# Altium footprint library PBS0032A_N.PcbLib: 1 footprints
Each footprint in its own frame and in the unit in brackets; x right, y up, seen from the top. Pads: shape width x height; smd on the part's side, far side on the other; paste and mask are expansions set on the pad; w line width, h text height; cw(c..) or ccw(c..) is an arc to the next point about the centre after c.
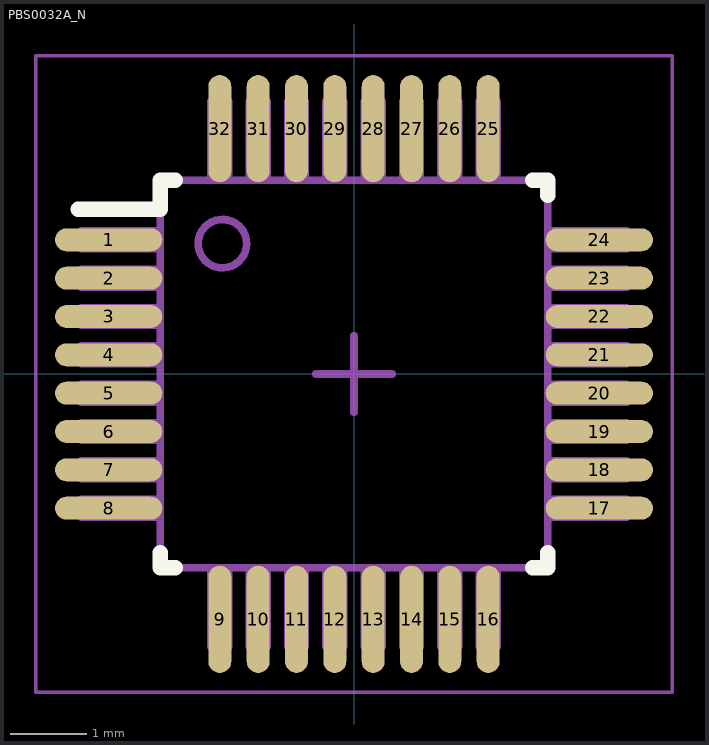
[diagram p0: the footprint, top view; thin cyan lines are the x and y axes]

## PBS0032A_N [mm]
height 1.2
pads (32):
  oval 1.4x0.3 smd: 1(-3.2,1.75) 2(-3.2,1.25) 3(-3.2,0.75) 4(-3.2,0.25) 5(-3.2,-0.25) 6(-3.2,-0.75) 7(-3.2,-1.25) 8(-3.2,-1.75) 17(3.2,-1.75) 18(3.2,-1.25) 19(3.2,-0.75) 20(3.2,-0.25) 21(3.2,0.25) 22(3.2,0.75) 23(3.2,1.25) 24(3.2,1.75)
  oval 0.3x1.4 smd: 9(-1.75,-3.2) 10(-1.25,-3.2) 11(-0.75,-3.2) 12(-0.25,-3.2) 13(0.25,-3.2) 14(0.75,-3.2) 15(1.25,-3.2) 16(1.75,-3.2) 25(1.75,3.2) 26(1.25,3.2) 27(0.75,3.2) 28(0.25,3.2) 29(-0.25,3.2) 30(-0.75,3.2) 31(-1.25,3.2) 32(-1.75,3.2)
Top Overlay:
  lines w0.2: -3.6,2.15 -2.527,2.15 -2.527,2.527 -2.327,2.527 ; -2.527,-2.327 -2.527,-2.527 -2.327,-2.527 ; 2.327,-2.527 2.527,-2.527 2.527,-2.327 ; 2.327,2.527 2.527,2.527 2.527,2.327
Mechanical 5:
  circle w0.1: c-1.716,1.7 r0.316
  lines w0.1: -3.556,-1.864 -3.556,-1.636 -2.527,-1.636 -2.527,-1.864 -3.556,-1.864 ; -3.556,-1.364 -3.556,-1.136 -2.527,-1.136 -2.527,-1.364 -3.556,-1.364 ; -3.556,-0.864 -3.556,-0.636 -2.527,-0.636 -2.527,-0.864 -3.556,-0.864 ; -3.556,-0.364 -3.556,-0.136 -2.527,-0.136 -2.527,-0.364 -3.556,-0.364 ; -3.556,0.136 -3.556,0.364 -2.527,0.364 -2.527,0.136 -3.556,0.136 ; -3.556,0.636 -3.556,0.864 -2.527,0.864 -2.527,0.636 -3.556,0.636 ; -3.556,1.136 -3.556,1.364 -2.527,1.364 -2.527,1.136 -3.556,1.136 ; -3.556,1.636 -3.556,1.864 -2.527,1.864 -2.527,1.636 -3.556,1.636 ; -2.527,-2.527 2.527,-2.527 2.527,2.527 -2.527,2.527 -2.527,-2.527 ; -1.864,-3.556 -1.864,-2.527 -1.636,-2.527 -1.636,-3.556 -1.864,-3.556 ; -1.864,2.527 -1.636,2.527 -1.636,3.556 -1.864,3.556 -1.864,2.527 ; -1.364,-3.556 -1.364,-2.527 -1.136,-2.527 -1.136,-3.556 -1.364,-3.556 ; -1.364,2.527 -1.136,2.527 -1.136,3.556 -1.364,3.556 -1.364,2.527 ; -0.864,-3.556 -0.864,-2.527 -0.636,-2.527 -0.636,-3.556 -0.864,-3.556 ; -0.864,2.527 -0.636,2.527 -0.636,3.556 -0.864,3.556 -0.864,2.527 ; -0.364,-3.556 -0.364,-2.527 -0.136,-2.527 -0.136,-3.556 -0.364,-3.556 ; -0.364,2.527 -0.136,2.527 -0.136,3.556 -0.364,3.556 -0.364,2.527 ; 0.136,-3.556 0.136,-2.527 0.364,-2.527 0.364,-3.556 0.136,-3.556 ; 0.136,2.527 0.364,2.527 0.364,3.556 0.136,3.556 0.136,2.527 ; 0.636,-3.556 0.636,-2.527 0.864,-2.527 0.864,-3.556 0.636,-3.556 ; 0.636,2.527 0.864,2.527 0.864,3.556 0.636,3.556 0.636,2.527 ; 1.136,-3.556 1.136,-2.527 1.364,-2.527 1.364,-3.556 1.136,-3.556 ; 1.136,2.527 1.364,2.527 1.364,3.556 1.136,3.556 1.136,2.527 ; 1.636,-3.556 1.636,-2.527 1.864,-2.527 1.864,-3.556 1.636,-3.556 ; 1.636,2.527 1.864,2.527 1.864,3.556 1.636,3.556 1.636,2.527 ; 2.527,-1.864 2.527,-1.636 3.556,-1.636 3.556,-1.864 2.527,-1.864 ; 2.527,-1.364 2.527,-1.136 3.556,-1.136 3.556,-1.364 2.527,-1.364 ; 2.527,-0.864 2.527,-0.636 3.556,-0.636 3.556,-0.864 2.527,-0.864 ; 2.527,-0.364 2.527,-0.136 3.556,-0.136 3.556,-0.364 2.527,-0.364 ; 2.527,0.136 2.527,0.364 3.556,0.364 3.556,0.136 2.527,0.136 ; 2.527,0.636 2.527,0.864 3.556,0.864 3.556,0.636 2.527,0.636 ; 2.527,1.136 2.527,1.364 3.556,1.364 3.556,1.136 2.527,1.136 ; 2.527,1.636 2.527,1.864 3.556,1.864 3.556,1.636 2.527,1.636
  text ".Designator" at -2.175,-0.6 h1.2
Mechanical 15:
  lines w0.05: -4.15,-4.15 4.15,-4.15 4.15,4.15 -4.15,4.15 -4.15,-4.15
  lines w0.1: -0.5,0 0.5,0 ; 0,-0.5 0,0.5
3D body: height 1.2, standoff 0, extent -3.505,-3.505 3.506,3.506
